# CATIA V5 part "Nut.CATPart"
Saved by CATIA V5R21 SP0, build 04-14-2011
Part number: Nut
Material "Nickel": density 8880 kg/m3, Young's modulus 2.14e+11 Pa, Poisson ratio 0.31, thermal expansion 1.31e-05 1/K
Bounding box of the stored display mesh (mm): x -25.981 to 25.981, y -29.226 to 29.226, z 0 to 20
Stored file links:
  G:\CATIA\NUT BOLT\Nut.CATPart
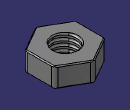
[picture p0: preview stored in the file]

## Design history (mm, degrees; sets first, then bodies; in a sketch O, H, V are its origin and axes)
AxisSystem1: origin (0, 0, 0), X (1, 0, 0), Y (0, 1, 0), Z (0, 0, 1)
Body1 (main body), material "Nickel"
  Sketch1 on XY plane of AxisSystem1, origin (0, 0, 0), H (0, 1, 0), V (-1, 0, 0)
    point P1 (15, 25.9808)
    point P2 (-15, 25.9808)
    point P3 (-30, 0)
    point P4 (-15, -25.9808)
    point P5 (15, -25.9808)
    point P6 (30, 0)
    point P7 (0, 25.9808)
    line L1 (15, 25.9808) -> (-15, 25.9808)
    line L2 (-15, 25.9808) -> (-30, 0)
    line L3 (-30, 0) -> (-15, -25.9808)
    line L4 (-15, -25.9808) -> (15, -25.9808)
    line L5 (15, -25.9808) -> (30, 0)
    line L6 (30, 0) -> (15, 25.9808)
    construction line L7 (0, 0) -> (0, 25.9808)
    construction circle A1 centre (0, 0) radius 30
    construction arc A2 centre (15, -25.9808) radius 30 from (-15, -25.9808) to (30, 0) cw
    construction arc A3 centre (-15, 25.9808) radius 30 from (-30, 0) to (15, 25.9808) ccw
    circle A4 centre (0, 0) radius 12.5
    length L6 = 30
    radius A4 = 12.5
    vertical: L7 V
    coincidence: A1 P1, A1 P2, A1 P3, A1 P4, A1 P5, A1 P6, A2 O, A3 O
    midpoint: P7 L1
    parallelism: L1 L4
  Pad1: profile Sketch1, direction (0, 0, 1), length 20
  Chamfer1: length 1, angle 45, on edge [face of Pad1 from Sketch1.L3 | end face of Pad1]; edge [face of Pad1 from Sketch1.L2 | end face of Pad1]; edge [face of Pad1 from Sketch1.L1 | end face of Pad1]; edge [face of Pad1 from Sketch1.L6 | end face of Pad1]; edge [face of Pad1 from Sketch1.L5 | end face of Pad1]; edge [face of Pad1 from Sketch1.L4 | end face of Pad1]; edge [start face of Pad1 | face of Pad1 from Sketch1.L1]; edge [start face of Pad1 | face of Pad1 from Sketch1.L2]; edge [start face of Pad1 | face of Pad1 from Sketch1.L3]; edge [start face of Pad1 | face of Pad1 from Sketch1.L4]; edge [start face of Pad1 | face of Pad1 from Sketch1.L5]; edge [start face of Pad1 | face of Pad1 from Sketch1.L6]
  Fillet1: radius 5, on edge [face of Pad1 from Sketch1.L1 | face of Pad1 from Sketch1.L6]; edge [face of Pad1 from Sketch1.L2 | face of Pad1 from Sketch1.L1]; edge [face of Pad1 from Sketch1.L6 | face of Pad1 from Sketch1.L5]; edge [face of Pad1 from Sketch1.L5 | face of Pad1 from Sketch1.L4]; edge [face of Pad1 from Sketch1.L4 | face of Pad1 from Sketch1.L3]; edge [face of Pad1 from Sketch1.L3 | face of Pad1 from Sketch1.L2]
  Point1: type OnCurve, Support edge [face of Pad1 from Sketch1.A4 | start face of Pad1], RefPoint {extremum Reference edge [face of Pad1 from Sketch1.A4 | start face of Pad1], Direction (1, 2, 3)}, Length 32.65
  Helix1: Direction Z axis, RefPoint Point1, Pitch 5, Height 22, TaperAngle 0
  Plane1: type Normal, Curve Helix1, RefPoint Point1
  Sketch2 on Plane1, origin (-10.4725, -6.8247, 0), H (0.8378, 0.546, 0), V (-0.0347, 0.0532, 0.998)
    circle A1 centre (0, 0) radius 1.5
    radius A1 = 1.5
  Slot1: profile Sketch2, centre curve Helix1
